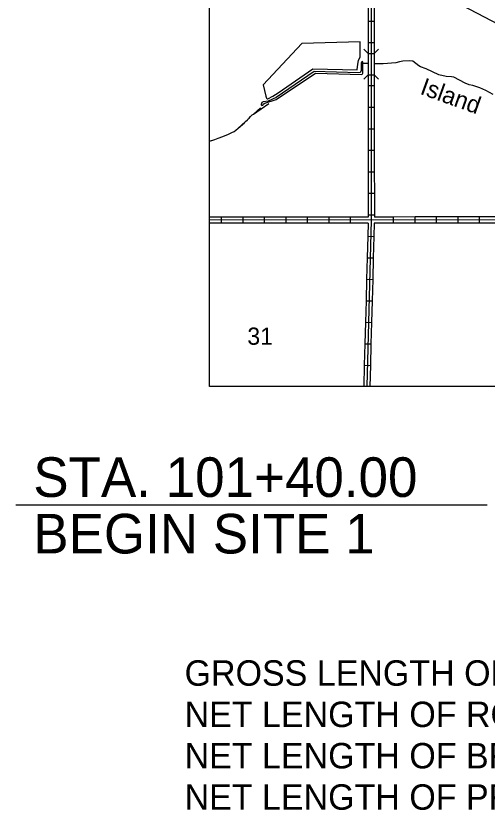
# Model space of a CAD drawing. Extents: x 982240 to 1103002, y 974866 to 1054902.
# Drawn here: x 1013864 to 1025433, y 977168 to 996650 of the extents above; entities that cross this region are included whole.
import ezdxf

# ---------------------------------------------------------------- set-up
doc = ezdxf.new("R2010")
doc.units = 0
for name, color, linetype in [('32', 7, 'Continuous'), ('35', 7, 'Continuous'), ('38', 7, 'Continuous'), ('43', 7, 'Continuous'), ('5', 7, 'Continuous'), ('R_Draft', 7, 'Continuous')]:
    doc.layers.add(name, color=color, linetype=linetype)

msp = doc.modelspace()

# ---------------------------------------------------------------- linework, layer by layer
at = {"layer": '32'}
for p, q in [((1022512, 996977), (1022512, 996523)), ((1022662, 996977), (1022662, 996523)), ((1022512, 996523), (1022662, 996523)), ((1022513, 995995), (1022663, 995995)), ((1022513, 995727), (1022663, 995727)), ((1022513, 995205), (1022663, 995205)), ((1022513, 994939), (1022663, 994939)), ((1022513, 994411), (1022663, 994411)), ((1022513, 993883), (1022663, 993883)), ((1022513, 993355), (1022663, 993355)), ((1022513, 992827), (1022663, 992827)), ((1022514, 992299), (1022664, 992299)), ((1018912, 991562), (1018912, 991712)), ((1019440, 991563), (1019440, 991713)), ((1019968, 991563), (1019968, 991713)), ((1020496, 991564), (1020496, 991714)), ((1021024, 991564), (1021024, 991714)), ((1021552, 991565), (1021552, 991715)), ((1022514, 991716), (1022080, 991715)), ((1022080, 991565), (1022080, 991715)), ((1022514, 991771), (1022664, 991771)), ((1022514, 991771), (1022514, 991716)), ((1022664, 991771), (1022664, 991716)), ((1023136, 991716), (1022664, 991716)), ((1023136, 991566), (1023136, 991716)), ((1023664, 991567), (1023664, 991717)), ((1024192, 991567), (1024192, 991717)), ((1024720, 991568), (1024720, 991718)), ((1025248, 991568), (1025248, 991718)), ((1022512, 991566), (1022080, 991565)), ((1022512, 991566), (1022503, 991245)), ((1022662, 991566), (1022653, 991241)), ((1023136, 991566), (1022662, 991566)), ((1022503, 991245), (1022653, 991241)), ((1022489, 990718), (1022639, 990714)), ((1022475, 990190), (1022625, 990186)), ((1022460, 989662), (1022610, 989658)), ((1022446, 989134), (1022596, 989130)), ((1022432, 988606), (1022582, 988602)), ((1022418, 988079), (1022568, 988075))]:
    msp.add_line(p, q, dxfattribs=at)
for points in [[(1022586, 997051), (1022587, 991642), (1022477, 987556)], [(1022512, 996523), (1022513, 995995)], [(1022662, 996523), (1022663, 995995)], [(1022513, 995995), (1022513, 995467)], [(1022663, 995995), (1022663, 995467)], [(1022513, 995467), (1022513, 994939)], [(1022663, 995467), (1022663, 994939)], [(1022513, 994939), (1022513, 994411)], [(1022663, 994939), (1022663, 994411)], [(1022513, 994411), (1022513, 993883)], [(1022663, 994411), (1022663, 993883)], [(1022513, 993883), (1022513, 993355)], [(1022663, 993883), (1022663, 993355)], [(1022513, 993355), (1022513, 992827)], [(1022663, 993355), (1022663, 992827)], [(1022513, 992827), (1022514, 992299)], [(1022663, 992827), (1022664, 992299)], [(1022514, 992299), (1022514, 991771)], [(1022664, 992299), (1022664, 991771)], [(1018912, 991712), (1018617, 991712)], [(1027888, 991644), (1018617, 991636)], [(1019440, 991713), (1018912, 991712)], [(1019968, 991713), (1019440, 991713)], [(1020496, 991714), (1019968, 991713)], [(1021024, 991714), (1020496, 991714)], [(1021552, 991715), (1021024, 991714)], [(1022080, 991715), (1021552, 991715)], [(1023664, 991717), (1023136, 991716)], [(1024192, 991717), (1023664, 991717)], [(1024720, 991718), (1024192, 991717)], [(1025248, 991718), (1024720, 991718)], [(1025776, 991719), (1025248, 991718)], [(1018912, 991562), (1018617, 991562)], [(1019440, 991563), (1018912, 991562)], [(1019968, 991563), (1019440, 991563)], [(1020496, 991564), (1019968, 991563)], [(1021024, 991564), (1020496, 991564)], [(1021552, 991565), (1021024, 991564)], [(1022080, 991565), (1021552, 991565)], [(1023664, 991567), (1023136, 991566)], [(1024192, 991567), (1023664, 991567)], [(1024720, 991568), (1024192, 991567)], [(1025248, 991568), (1024720, 991568)], [(1025776, 991569), (1025248, 991568)], [(1022503, 991245), (1022489, 990718)], [(1022653, 991241), (1022639, 990714)], [(1022489, 990718), (1022475, 990190)], [(1022639, 990714), (1022625, 990186)], [(1022475, 990190), (1022460, 989662)], [(1022625, 990186), (1022610, 989658)], [(1022460, 989662), (1022446, 989134)], [(1022610, 989658), (1022596, 989130)], [(1022446, 989134), (1022432, 988606)], [(1022596, 989130), (1022582, 988602)], [(1022432, 988606), (1022418, 988079)], [(1022582, 988602), (1022568, 988075)], [(1022418, 988079), (1022404, 987556)], [(1022568, 988075), (1022554, 987556)]]:
    msp.add_lwpolyline(points, dxfattribs=at)
at = {"layer": '35'}
for points in [[(1022313, 996013), (1020886, 995972), (1019933, 994955), (1019998, 994680), (1020016, 994628), (1020029, 994619), (1020051, 994617), (1020175, 994679), (1020305, 994762), (1021154, 995351), (1022242, 995329), (1022257, 995467), (1022276, 995556), (1022320, 995644)], [(1022320, 995644), (1022313, 996013)], [(1022513, 995480), (1022382, 995479), (1022378, 995523), (1022363, 995527), (1022350, 995518), (1022342, 995497), (1022339, 995310), (1022325, 995267), (1022313, 995258), (1022284, 995255), (1021188, 995282), (1020257, 994645), (1020056, 994559), (1019934, 994545), (1019906, 994522), (1019897, 994502)], [(1025580, 994720), (1025404, 994822), (1025257, 994889), (1025078, 994946), (1024990, 994962), (1024896, 995000), (1024612, 995144), (1024555, 995158), (1024430, 995161), (1024251, 995203), (1023940, 995349), (1023800, 995403), (1023753, 995426), (1023607, 995537), (1023516, 995550), (1023366, 995543), (1023278, 995522), (1023191, 995497), (1022879, 995477), (1022663, 995476)], [(1019897, 994502), (1019888, 994480), (1019889, 994464), (1019904, 994450), (1019928, 994462), (1019950, 994493), (1019972, 994510), (1020251, 994597), (1021216, 995248), (1022354, 995213), (1022372, 995226), (1022381, 995245), (1022382, 995479)]]:
    msp.add_lwpolyline(points, dxfattribs=at)
at = {"layer": '38'}
for points in [[(1022513, 995727), (1022407, 995834)], [(1022769, 995833), (1022663, 995727)], [(1022406, 995099), (1022513, 995205)], [(1022663, 995205), (1022769, 995098)]]:
    msp.add_lwpolyline(points, dxfattribs=at)
at = {"layer": '43'}
for points in [[(1018617, 993576), (1018645, 993584), (1018745, 993619), (1018833, 993652), (1018944, 993691), (1019068, 993737), (1019101, 993756), (1019166, 993786), (1019220, 993815), (1019264, 993847), (1019318, 993893), (1019503, 994056), (1019550, 994102), (1019591, 994143), (1019623, 994178), (1019642, 994199), (1019665, 994221), (1019697, 994242), (1020072, 994498)], [(1019568, 994121), (1019591, 994143), (1019623, 994178), (1019642, 994199), (1019665, 994221), (1019697, 994242), (1019872, 994396)], [(1019164, 993785), (1019166, 993786), (1019220, 993815), (1019264, 993847), (1019318, 993893), (1019473, 994030)], [(1018672, 993593), (1018745, 993619), (1018833, 993652), (1018944, 993691), (1019044, 993728)]]:
    msp.add_lwpolyline(points, dxfattribs=at)
at = {"layer": 'R_Draft'}
for p, q in [((1016927, 1001150), (1027889, 995273)), ((1025433, 984647), (1013864, 984647))]:
    msp.add_line(p, q, dxfattribs=at)
msp.add_lwpolyline([(1018617, 1018049), (1063840, 1018049), (1063840, 987556), (1018617, 987556)], close=True, dxfattribs=at)
msp.add_lwpolyline([(1018617, 1018049), (1063840, 1018049), (1063840, 987556), (1018617, 987556)], close=True, dxfattribs=at)

# ---------------------------------------------------------------- texts
at = {"layer": '35'}
msp.add_text('Island', height=422.4, rotation=340.2554, dxfattribs=at).set_placement((1023763, 994742))
at = {"layer": '5'}
msp.add_text('31', height=422.4, dxfattribs=at).set_placement((1019546, 988582))
at = {"layer": 'R_Draft'}
for s, height, p in [('STA. 101+40.00', 972, (1014292, 984850)), ('BEGIN SITE 1', 972, (1014292, 983463)), ('GROSS LENGTH OF PROJECT', 624, (1018006, 980219)), ('NET LENGTH OF ROADWAY', 624, (1018006, 979205)), ('NET LENGTH OF BRIDGES', 624, (1018006, 978191)), ('NET LENGTH OF PROJECT', 624, (1018006, 977177))]:
    msp.add_text(s, height=height, dxfattribs=at).set_placement(p)

doc.saveas('drawing.dxf')
